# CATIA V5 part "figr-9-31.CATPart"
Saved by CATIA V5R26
Part number: Part1
Bounding box of the stored display mesh (mm): x -60 to 60, y -41.231 to 41.231, z -41.231 to 41.231
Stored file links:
  D:\_Deepak\CATIA\CATIA V5-6R2016_Deepak\Resources\Part files\Partfiles\c09_catia_v5_6r2016_prt\figr-9-31.CATPart
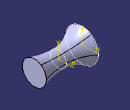
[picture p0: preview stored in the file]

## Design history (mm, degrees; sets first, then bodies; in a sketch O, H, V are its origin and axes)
Body1 (main body)
  Sketch1 on yz-plane, origin (0, 0, 0), H (0, 1, 0), V (0, 0, 1)
    circle A1 centre (0, 0) radius 20
  Plane1: type Offset, RefPlane yz-plane, Offset 60
  Plane2: type Offset, RefPlane yz-plane, Offset -60
  Sketch2 on Plane1, origin (60, 0, 0), H (0, 1, 0), V (0, 0, 1)
    circle A1 centre (0, 0) radius 30
  Sketch3 on Plane2, origin (-60, 0, 0), H (0, 1, 0), V (0, 0, 1)
    circle A1 centre (0, 0) radius 41.2311
  Loft1: solid, Sections (Sketch2; Sketch1; Sketch3)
